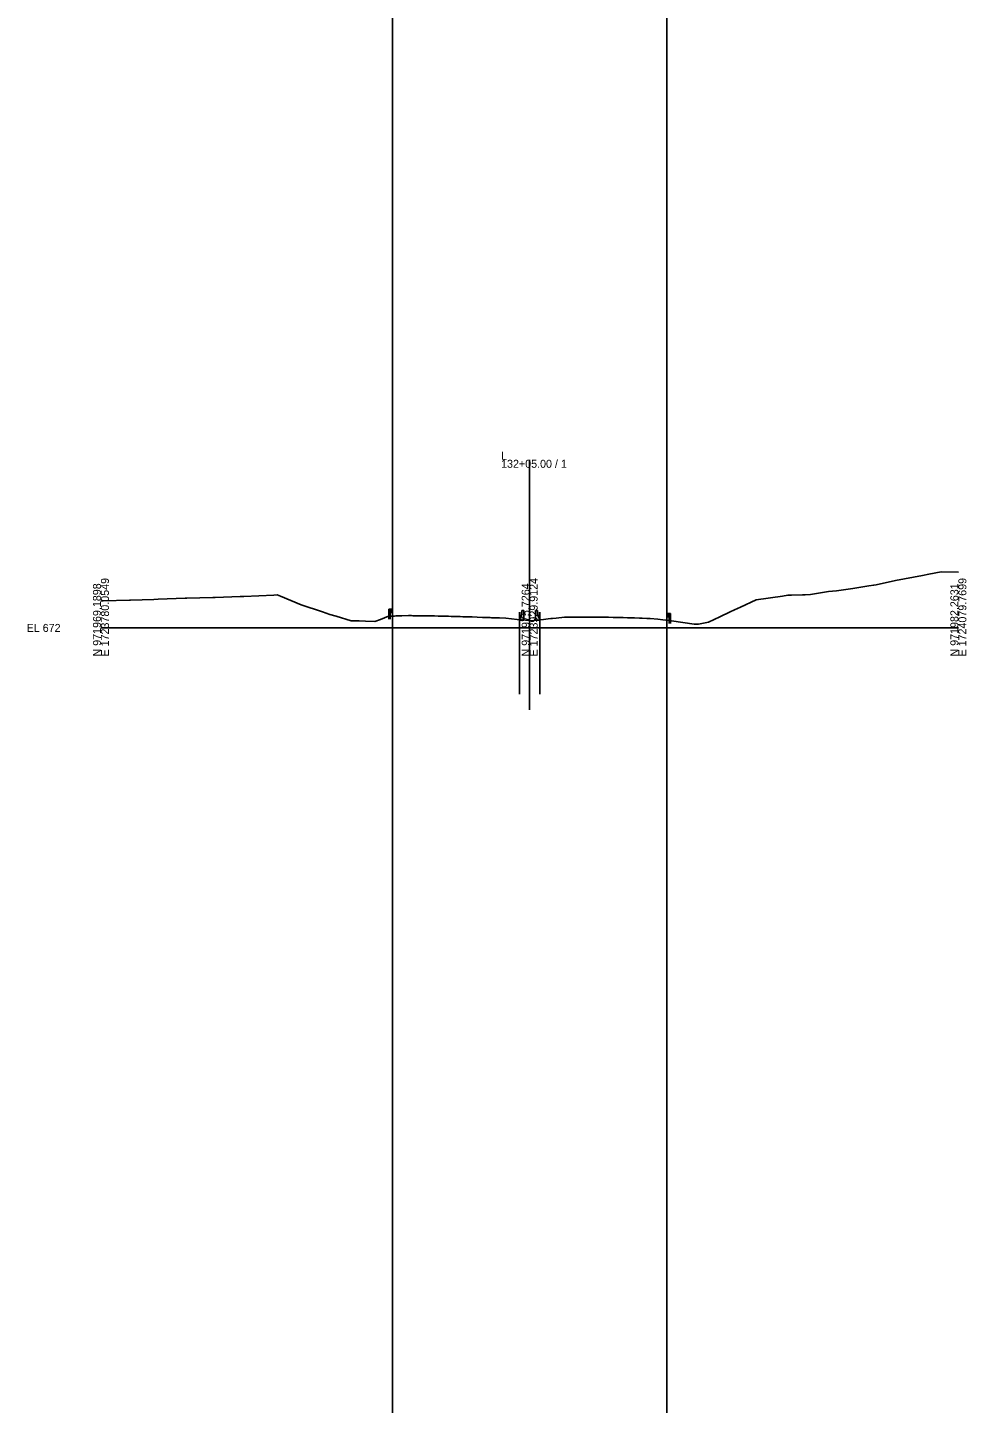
# Model space of a CAD drawing. Extents: x -26 to 303, y -29 to 15026.
# Drawn here: x -25.7 to 302.8, y 9728.6 to 10210.1 of the extents above; entities that cross this region are included whole.
import ezdxf

# ---------------------------------------------------------------- set-up
doc = ezdxf.new("R2010")
doc.units = 0
for name, color, linetype in [('Exist Cross Section Cell', 7, 'Continuous'), ('Exist XS Center Line Elevation Label', 7, 'Continuous'), ('Exist XS Ground Line', 7, 'Continuous'), ('Scratch_Level_0', 7, 'Continuous'), ('Typical Guardrail CELL', 7, 'Continuous'), ('Typical Median Barrier CELL', 7, 'Continuous')]:
    doc.layers.add(name, color=color, linetype=linetype)

msp = doc.modelspace()

# ---------------------------------------------------------------- linework, layer by layer
at = {"layer": 'Exist Cross Section Cell'}
for p, q in [((150, 10000), (150, 10058.85)), ((0, 10000), (150, 10000)), ((150, 10000), (300, 10000))]:
    msp.add_line(p, q, dxfattribs=at)
at = {"layer": 'Exist XS Ground Line'}
msp.add_lwpolyline([(0, 10009.4), (0.73, 10009.43), (9.97, 10009.75), (10.33, 10009.76), (18.53, 10009.98), (19.98, 10010.02), (29.51, 10010.39), (29.99, 10010.39), (39.1, 10010.62), (39.99, 10010.66), (48.69, 10011), (50, 10011.05), (60.48, 10011.52), (61.69, 10011.54), (62.78, 10011.16), (70.02, 10008.07), (77.46, 10005.59), (80.03, 10004.74), (82.35, 10004.07), (87.57, 10002.5), (90.34, 10002.46), (92.51, 10002.4), (95.86, 10002.2), (97.77, 10002.95), (100.64, 10004.08), (102.01, 10004.15), (102.32, 10004.16), (102.69, 10004.17), (103.23, 10004.19), (104.02, 10004.21), (105.23, 10004.24), (107.56, 10004.3), (108.63, 10004.3), (109.16, 10004.29), (111.36, 10004.28), (111.71, 10004.27), (114.17, 10004.22), (115.24, 10004.2), (116.67, 10004.18), (117.98, 10004.15), (119.16, 10004.12), (120.37, 10004.09), (121.65, 10004.06), (122.5, 10004.04), (123.09, 10004.03), (123.58, 10004.02), (124.14, 10004), (125.66, 10003.96), (126.64, 10003.93), (128.29, 10003.89), (129.15, 10003.86), (129.93, 10003.84), (131.65, 10003.78), (133.53, 10003.7), (134.15, 10003.68), (135, 10003.65), (135.7, 10003.62), (136.2, 10003.6), (136.65, 10003.58), (138.76, 10003.52), (139.15, 10003.51), (139.46, 10003.5), (141.7, 10003.4), (145.63, 10002.98), (150, 10002.55), (150.35, 10002.52), (154.88, 10002.96), (156.49, 10003.17), (157.4, 10003.27), (157.98, 10003.33), (159.27, 10003.45), (162.21, 10003.71), (163.3, 10003.72), (164.23, 10003.73), (165.89, 10003.74), (166.73, 10003.74), (167.57, 10003.75), (169.2, 10003.76), (170.73, 10003.77), (171.73, 10003.77), (172.8, 10003.77), (174.21, 10003.77), (176.48, 10003.76), (177.1, 10003.76), (177.63, 10003.75), (179.21, 10003.7), (180.3, 10003.67), (181.7, 10003.64), (182.68, 10003.62), (184.2, 10003.58), (185.85, 10003.53), (186.69, 10003.5), (188.46, 10003.45), (189.34, 10003.42), (191, 10003.35), (191.61, 10003.33), (192.2, 10003.28), (194.79, 10003.03), (196.55, 10002.86), (199.61, 10002.52), (207.6, 10001.35), (208.45, 10001.26), (209.06, 10001.36), (212.62, 10001.97), (216.53, 10003.84), (220.16, 10005.66), (221.7, 10006.38), (223.82, 10007.32), (229.2, 10009.82), (238.44, 10011.13), (240.36, 10011.42), (241.61, 10011.42), (245.49, 10011.56), (246.43, 10011.6), (248.27, 10011.69), (254.53, 10012.72), (257.35, 10012.95), (263.05, 10013.76), (268.66, 10014.68), (270.41, 10015.01), (271.21, 10015.12), (277.95, 10016.58), (287.48, 10018.39), (289.66, 10018.76), (293.98, 10019.62), (300, 10019.5)], dxfattribs=at)
at = {"layer": 'Scratch_Level_0'}
for p, q in [((102, 15009.56), (102, -28.7)), ((198, 15009.56), (198, -28.7)), ((146.46, 10005.5), (146.46, 9976.8)), ((153.54, 10005.5), (153.54, 9976.8)), ((150, 10000), (150, 9971.3)), ((150, 10000), (150, 9971.3))]:
    msp.add_line(p, q, dxfattribs=at)
at = {"layer": 'Typical Guardrail CELL'}
for p, q in [((101.18, 10006.57), (100.68, 10006.57)), ((100.68, 10006.57), (100.68, 10004.09)), ((101.18, 10004.09), (100.68, 10004.09)), ((100.68, 10004.09), (100.68, 10003.08)), ((101.18, 10006.57), (101.18, 10004.09)), ((101.18, 10006.57), (101.68, 10006.57)), ((101.18, 10005.41), (101.68, 10005.41)), ((101.18, 10004.09), (101.18, 10003.08)), ((101.68, 10006.57), (101.68, 10005.41)), ((101.68, 10006.57), (101.97, 10006.37)), ((101.68, 10006.04), (101.97, 10006.24)), ((101.68, 10005.99), (101.68, 10006.04)), ((101.68, 10005.99), (101.68, 10005.95)), ((101.68, 10005.95), (101.97, 10005.74)), ((101.68, 10005.41), (101.97, 10005.61)), ((198.32, 10005.04), (198.03, 10004.84)), ((198.32, 10004.51), (198.03, 10004.71)), ((198.32, 10004.41), (198.03, 10004.21)), ((198.32, 10003.88), (198.03, 10004.08)), ((198.82, 10005.04), (198.32, 10005.04)), ((198.32, 10005.04), (198.32, 10003.88)), ((198.32, 10004.46), (198.32, 10004.51)), ((198.32, 10004.46), (198.32, 10004.41)), ((198.82, 10003.88), (198.32, 10003.88)), ((198.82, 10005.04), (198.82, 10002.55)), ((198.82, 10005.04), (199.32, 10005.04)), ((198.82, 10002.55), (199.32, 10002.55)), ((198.82, 10002.55), (198.82, 10001.55)), ((199.32, 10005.04), (199.32, 10002.55)), ((199.32, 10002.55), (199.32, 10001.55))]:
    msp.add_line(p, q, dxfattribs=at)
for centre, start, end in [((101.92, 10006.31), 304.9888, 54.997), ((101.92, 10005.68), 304.9634, 54.9941), ((198.08, 10004.77), 125.003, 235.0112), ((198.08, 10004.15), 125.0059, 235.0366)]:
    msp.add_arc(centre, 0.0776, start, end, dxfattribs=at)
at = {"layer": 'Typical Median Barrier CELL'}
for p, q in [((146.46, 10003.09), (146.92, 10003.74)), ((146.46, 10002.67), (146.46, 10003.09)), ((147.96, 10002.67), (146.46, 10002.67)), ((147.07, 10004.13), (147.29, 10006.09)), ((147.29, 10006.09), (147.96, 10006.09)), ((147.96, 10006.09), (147.96, 10002.67)), ((152.71, 10006.09), (152.04, 10006.09)), ((152.04, 10006.09), (152.04, 10002.67)), ((152.04, 10002.67), (153.54, 10002.67)), ((152.93, 10004.13), (152.71, 10006.09)), ((153.54, 10003.09), (153.08, 10003.74)), ((153.54, 10002.67), (153.54, 10003.09))]:
    msp.add_line(p, q, dxfattribs=at)
for centre, start, end in [((146.24, 10004.22), 325.0039, 353.9447), ((153.76, 10004.22), 186.0553, 214.9961)]:
    msp.add_arc(centre, 0.833, start, end, dxfattribs=at)

# ---------------------------------------------------------------- texts
at = {"layer": 'Exist Cross Section Cell'}
for s, p in [('L', (140, 10058.85)), ('132+05.00 / 1', (140, 10056.05)), ('EL 672', (-26, 9998.6))]:
    msp.add_text(s, height=2.8, dxfattribs=at).set_placement(p)
for s, p in [('E 1723780.0549', (2.8, 9990)), ('E 1723929.9124', (152.8, 9990)), ('E 1724079.7699', (302.8, 9990)), ('N 971969.1898', (0, 9990)), ('N 971975.7264', (150, 9990)), ('N 971982.2631', (300, 9990))]:
    msp.add_text(s, height=2.8, rotation=90, dxfattribs=at).set_placement(p)
at = {"layer": 'Exist XS Center Line Elevation Label'}
msp.add_text('674.55', height=0.18, dxfattribs=at).set_placement((149.62, 10002.06))

doc.saveas('drawing.dxf')
